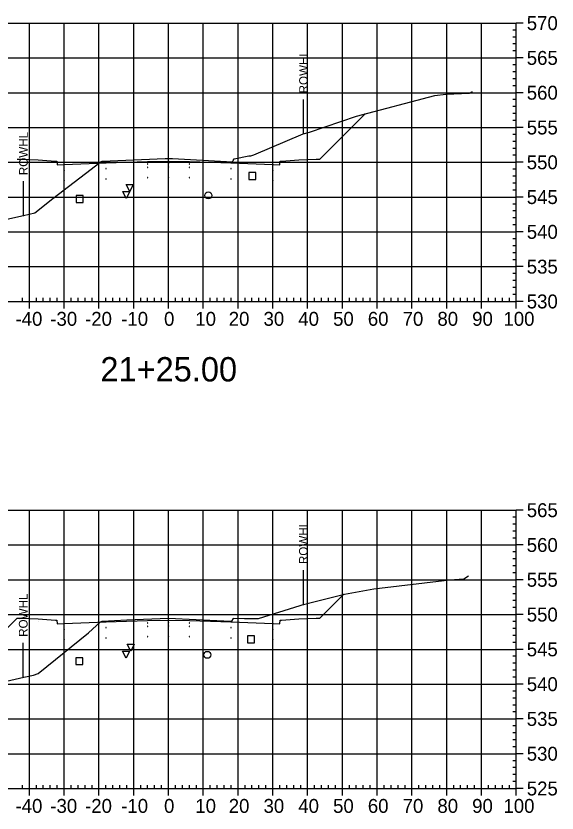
# Model space of a CAD drawing. Extents: x 708103 to 717568, y 374476 to 378707.
# Drawn here: x 709283.1 to 709438.7, y 377827.6 to 378056.7 of the extents above; entities that cross this region are included whole.
import ezdxf

# ---------------------------------------------------------------- set-up
doc = ezdxf.new("R2010")
doc.units = 0
for name, color, linetype in [('1', 7, 'Continuous'), ('10', 7, 'Continuous'), ('13', 7, 'Continuous'), ('14', 7, 'Continuous'), ('22', 7, 'Continuous'), ('4', 7, 'Continuous'), ('57', 7, 'Continuous'), ('Existing', 7, 'Continuous'), ('XS_Right_of_Way', 7, 'Continuous')]:
    doc.layers.add(name, color=color, linetype=linetype)

msp = doc.modelspace()

# ---------------------------------------------------------------- linework, layer by layer
for points in [[(709296.93, 378012.28), (709297.03, 378012.28), (709297.03, 378012.38), (709296.93, 378012.38)], [(709308.93, 378012.76), (709309.03, 378012.76), (709309.03, 378012.86), (709308.93, 378012.86)], [(709320.93, 378014.12), (709321.03, 378014.12), (709321.03, 378014.22), (709320.93, 378014.22)], [(709320.93, 378013.12), (709321.03, 378013.12), (709321.03, 378013.22), (709320.93, 378013.22)], [(709326.93, 378014.24), (709327.03, 378014.24), (709327.03, 378014.34), (709326.93, 378014.34)], [(709326.93, 378013.24), (709327.03, 378013.24), (709327.03, 378013.34), (709326.93, 378013.34)], [(709332.93, 378014.12), (709333.03, 378014.12), (709333.03, 378014.22), (709332.93, 378014.22)], [(709332.93, 378013.12), (709333.03, 378013.12), (709333.03, 378013.22), (709332.93, 378013.22)], [(709344.93, 378012.76), (709345.03, 378012.76), (709345.03, 378012.86), (709344.93, 378012.86)], [(709356.93, 378012.28), (709357.03, 378012.28), (709357.03, 378012.38), (709356.93, 378012.38)], [(709320.93, 378010.12), (709321.03, 378010.12), (709321.03, 378010.22), (709320.93, 378010.22)], [(709326.93, 378010.24), (709327.03, 378010.24), (709327.03, 378010.34), (709326.93, 378010.34)], [(709332.93, 378010.12), (709333.03, 378010.12), (709333.03, 378010.22), (709332.93, 378010.22)], [(709296.93, 378009.28), (709297.03, 378009.28), (709297.03, 378009.38), (709296.93, 378009.38)], [(709308.93, 378009.76), (709309.03, 378009.76), (709309.03, 378009.86), (709308.93, 378009.86)], [(709344.93, 378009.76), (709345.03, 378009.76), (709345.03, 378009.86), (709344.93, 378009.86)], [(709356.93, 378009.28), (709357.03, 378009.28), (709357.03, 378009.38), (709356.93, 378009.38)], [(709320.93, 377882.2), (709321.03, 377882.2), (709321.03, 377882.3), (709320.93, 377882.3)], [(709326.93, 377882.32), (709327.03, 377882.32), (709327.03, 377882.42), (709326.93, 377882.42)], [(709332.93, 377882.2), (709333.03, 377882.2), (709333.03, 377882.3), (709332.93, 377882.3)], [(709296.93, 377880.36), (709297.03, 377880.36), (709297.03, 377880.46), (709296.93, 377880.46)], [(709308.93, 377880.84), (709309.03, 377880.84), (709309.03, 377880.94), (709308.93, 377880.94)], [(709320.93, 377881.2), (709321.03, 377881.2), (709321.03, 377881.3), (709320.93, 377881.3)], [(709326.93, 377881.32), (709327.03, 377881.32), (709327.03, 377881.42), (709326.93, 377881.42)], [(709332.93, 377881.2), (709333.03, 377881.2), (709333.03, 377881.3), (709332.93, 377881.3)], [(709344.93, 377880.84), (709345.03, 377880.84), (709345.03, 377880.94), (709344.93, 377880.94)], [(709356.93, 377880.36), (709357.03, 377880.36), (709357.03, 377880.46), (709356.93, 377880.46)], [(709296.93, 377877.36), (709297.03, 377877.36), (709297.03, 377877.46), (709296.93, 377877.46)], [(709308.93, 377877.84), (709309.03, 377877.84), (709309.03, 377877.94), (709308.93, 377877.94)], [(709320.93, 377878.2), (709321.03, 377878.2), (709321.03, 377878.3), (709320.93, 377878.3)], [(709326.93, 377878.32), (709327.03, 377878.32), (709327.03, 377878.42), (709326.93, 377878.42)], [(709332.93, 377878.2), (709333.03, 377878.2), (709333.03, 377878.3), (709332.93, 377878.3)], [(709344.93, 377877.84), (709345.03, 377877.84), (709345.03, 377877.94), (709344.93, 377877.94)], [(709356.93, 377877.36), (709357.03, 377877.36), (709357.03, 377877.46), (709356.93, 377877.46)]]:
    msp.add_lwpolyline(points, close=True)
at = {"layer": '1'}
for points in [[(709315.82, 378006.27), (709314.82, 378008.27), (709316.82, 378008.27)], [(709314.84, 378004.23), (709313.84, 378006.23), (709315.84, 378006.23)], [(709316.13, 377874.14), (709315.13, 377876.14), (709317.13, 377876.14)], [(709314.76, 377872.08), (709313.76, 377874.08), (709315.76, 377874.08)]]:
    msp.add_lwpolyline(points, close=True, dxfattribs=at)
at = {"layer": '10'}
for points in [[(709300.41, 378003.08), (709302.41, 378003.08), (709302.41, 378005.08), (709300.41, 378005.08)], [(709300.33, 377870.24), (709302.33, 377870.24), (709302.33, 377872.24), (709300.33, 377872.24)]]:
    msp.add_lwpolyline(points, close=True, dxfattribs=at)
at = {"layer": '13'}
for centre in [(709338.42, 378005.12), (709338.14, 377873.06)]:
    msp.add_circle(centre, 1, dxfattribs=at)
at = {"layer": '14'}
for points in [[(709383.42, 378028.49), (709383.42, 378028.54), (709383.42, 378028.49), (709383.37, 378028.49), (709383.42, 378028.49), (709383.42, 378028.44), (709383.42, 378028.49), (709383.47, 378028.49)], [(709326.98, 378014.96), (709326.98, 378015.01), (709326.98, 378014.96), (709326.93, 378014.96), (709326.98, 378014.96), (709326.98, 378014.91), (709326.98, 378014.96), (709327.03, 378014.96)], [(709296.98, 378014), (709296.98, 378014.05), (709296.98, 378014), (709296.93, 378014), (709296.98, 378014), (709296.98, 378013.95), (709296.98, 378014), (709297.03, 378014)], [(709308.98, 378014.48), (709308.98, 378014.53), (709308.98, 378014.48), (709308.93, 378014.48), (709308.98, 378014.48), (709308.98, 378014.43), (709308.98, 378014.48), (709309.03, 378014.48)], [(709344.98, 378014.48), (709344.98, 378014.53), (709344.98, 378014.48), (709344.93, 378014.48), (709344.98, 378014.48), (709344.98, 378014.43), (709344.98, 378014.48), (709345.03, 378014.48)], [(709356.98, 378014), (709356.98, 378014.05), (709356.98, 378014), (709356.93, 378014), (709356.98, 378014), (709356.98, 378013.95), (709356.98, 378014), (709357.03, 378014)], [(709377.25, 377890.4), (709377.25, 377890.45), (709377.25, 377890.4), (709377.2, 377890.4), (709377.25, 377890.4), (709377.25, 377890.35), (709377.25, 377890.4), (709377.3, 377890.4)], [(709296.98, 377882.08), (709296.98, 377882.13), (709296.98, 377882.08), (709296.93, 377882.08), (709296.98, 377882.08), (709296.98, 377882.03), (709296.98, 377882.08), (709297.03, 377882.08)], [(709308.98, 377882.56), (709308.98, 377882.61), (709308.98, 377882.56), (709308.93, 377882.56), (709308.98, 377882.56), (709308.98, 377882.51), (709308.98, 377882.56), (709309.03, 377882.56)], [(709326.98, 377883.04), (709326.98, 377883.09), (709326.98, 377883.04), (709326.93, 377883.04), (709326.98, 377883.04), (709326.98, 377882.99), (709326.98, 377883.04), (709327.03, 377883.04)], [(709344.98, 377882.56), (709344.98, 377882.61), (709344.98, 377882.56), (709344.93, 377882.56), (709344.98, 377882.56), (709344.98, 377882.51), (709344.98, 377882.56), (709345.03, 377882.56)], [(709356.98, 377882.08), (709356.98, 377882.13), (709356.98, 377882.08), (709356.93, 377882.08), (709356.98, 377882.08), (709356.98, 377882.03), (709356.98, 377882.08), (709357.03, 377882.08)]]:
    msp.add_lwpolyline(points, dxfattribs=at)
at = {"layer": '22'}
for points in [[(709283.48, 378015.56), (709284.48, 378015.52), (709289.48, 378015.32), (709294.48, 378014.92), (709294.9, 378014.92), (709294.98, 378013.92), (709296.98, 378014), (709308.98, 378014.48), (709320.98, 378014.84), (709326.98, 378014.96), (709332.98, 378014.84), (709344.98, 378014.48), (709356.98, 378014), (709358.98, 378013.92), (709359.07, 378014.92), (709359.48, 378014.92), (709364.48, 378015.32), (709369.48, 378015.52), (709370.48, 378015.56), (709383.42, 378028.49)], [(709263.92, 377864.07), (709283.48, 377883.64), (709284.48, 377883.6), (709289.48, 377883.4), (709294.48, 377883), (709294.9, 377883), (709294.98, 377882), (709296.98, 377882.08), (709308.98, 377882.56), (709320.98, 377882.92), (709326.98, 377883.04), (709332.98, 377882.92), (709344.98, 377882.56), (709356.98, 377882.08), (709358.98, 377882), (709359.07, 377883), (709359.48, 377883), (709364.48, 377883.4), (709369.48, 377883.6), (709370.48, 377883.64), (709377.25, 377890.4)]]:
    msp.add_lwpolyline(points, dxfattribs=at)
at = {"layer": '4'}
for points in [[(709350.05, 378009.65), (709352.05, 378009.65), (709352.05, 378011.65), (709350.05, 378011.65)], [(709349.72, 377876.51), (709351.72, 377876.51), (709351.72, 377878.51), (709349.72, 377878.51)]]:
    msp.add_lwpolyline(points, close=True, dxfattribs=at)
at = {"layer": '57'}
for p, q in [((709226.98, 378054.63), (709426.98, 378054.63)), ((709286.98, 377974.63), (709286.98, 378054.63)), ((709296.98, 377974.63), (709296.98, 378054.63)), ((709306.98, 377974.63), (709306.98, 378054.63)), ((709316.98, 377974.63), (709316.98, 378054.63)), ((709326.98, 377974.63), (709326.98, 378054.63)), ((709336.98, 377974.63), (709336.98, 378054.63)), ((709346.98, 377974.63), (709346.98, 378054.63)), ((709356.98, 377974.63), (709356.98, 378054.63)), ((709366.98, 377974.63), (709366.98, 378054.63)), ((709376.98, 377974.63), (709376.98, 378054.63)), ((709386.98, 377974.63), (709386.98, 378054.63)), ((709396.98, 377974.63), (709396.98, 378054.63)), ((709406.98, 377974.63), (709406.98, 378054.63)), ((709416.98, 377974.63), (709416.98, 378054.63)), ((709426.98, 377974.63), (709426.98, 378054.63)), ((709426.98, 377974.63), (709426.98, 378054.63)), ((709428.98, 378054.63), (709426.98, 378054.63)), ((709426.98, 378052.63), (709425.98, 378052.63)), ((709426.98, 378050.63), (709425.98, 378050.63)), ((709426.98, 378048.63), (709425.98, 378048.63)), ((709426.98, 378046.63), (709425.98, 378046.63)), ((709226.98, 378044.63), (709426.98, 378044.63)), ((709428.98, 378044.63), (709426.98, 378044.63)), ((709426.98, 378042.63), (709425.98, 378042.63)), ((709426.98, 378040.63), (709425.98, 378040.63)), ((709426.98, 378038.63), (709425.98, 378038.63)), ((709426.98, 378036.63), (709425.98, 378036.63)), ((709226.98, 378034.63), (709426.98, 378034.63)), ((709428.98, 378034.63), (709426.98, 378034.63)), ((709426.98, 378032.63), (709425.98, 378032.63)), ((709426.98, 378030.63), (709425.98, 378030.63)), ((709426.98, 378028.63), (709425.98, 378028.63)), ((709426.98, 378026.63), (709425.98, 378026.63)), ((709226.98, 378024.63), (709426.98, 378024.63)), ((709428.98, 378024.63), (709426.98, 378024.63)), ((709426.98, 378022.63), (709425.98, 378022.63)), ((709426.98, 378020.63), (709425.98, 378020.63)), ((709426.98, 378018.63), (709425.98, 378018.63)), ((709226.98, 378014.63), (709426.98, 378014.63)), ((709426.98, 378016.63), (709425.98, 378016.63)), ((709428.98, 378014.63), (709426.98, 378014.63)), ((709426.98, 378012.63), (709425.98, 378012.63)), ((709426.98, 378010.63), (709425.98, 378010.63)), ((709426.98, 378008.63), (709425.98, 378008.63)), ((709426.98, 378006.63), (709425.98, 378006.63)), ((709226.98, 378004.63), (709426.98, 378004.63)), ((709428.98, 378004.63), (709426.98, 378004.63)), ((709426.98, 378002.63), (709425.98, 378002.63)), ((709426.98, 378000.63), (709425.98, 378000.63)), ((709426.98, 377998.63), (709425.98, 377998.63)), ((709426.98, 377996.63), (709425.98, 377996.63)), ((709226.98, 377994.63), (709426.98, 377994.63)), ((709428.98, 377994.63), (709426.98, 377994.63)), ((709426.98, 377992.63), (709425.98, 377992.63)), ((709426.98, 377990.63), (709425.98, 377990.63)), ((709426.98, 377988.63), (709425.98, 377988.63)), ((709426.98, 377986.63), (709425.98, 377986.63)), ((709226.98, 377984.63), (709426.98, 377984.63)), ((709426.98, 377982.63), (709425.98, 377982.63)), ((709428.98, 377984.63), (709426.98, 377984.63)), ((709426.98, 377980.63), (709425.98, 377980.63)), ((709426.98, 377978.63), (709425.98, 377978.63)), ((709284.98, 377974.63), (709284.98, 377975.63)), ((709288.98, 377974.63), (709288.98, 377975.63)), ((709290.98, 377974.63), (709290.98, 377975.63)), ((709292.98, 377974.63), (709292.98, 377975.63)), ((709294.98, 377974.63), (709294.98, 377975.63)), ((709298.98, 377974.63), (709298.98, 377975.63)), ((709300.98, 377974.63), (709300.98, 377975.63)), ((709302.98, 377974.63), (709302.98, 377975.63)), ((709304.98, 377974.63), (709304.98, 377975.63)), ((709308.98, 377974.63), (709308.98, 377975.63)), ((709310.98, 377974.63), (709310.98, 377975.63)), ((709312.98, 377974.63), (709312.98, 377975.63)), ((709314.98, 377974.63), (709314.98, 377975.63)), ((709318.98, 377974.63), (709318.98, 377975.63)), ((709320.98, 377974.63), (709320.98, 377975.63)), ((709322.98, 377974.63), (709322.98, 377975.63)), ((709324.98, 377974.63), (709324.98, 377975.63)), ((709328.98, 377974.63), (709328.98, 377975.63)), ((709330.98, 377974.63), (709330.98, 377975.63)), ((709332.98, 377974.63), (709332.98, 377975.63)), ((709334.98, 377974.63), (709334.98, 377975.63)), ((709338.98, 377974.63), (709338.98, 377975.63)), ((709340.98, 377974.63), (709340.98, 377975.63)), ((709342.98, 377974.63), (709342.98, 377975.63)), ((709344.98, 377974.63), (709344.98, 377975.63)), ((709348.98, 377974.63), (709348.98, 377975.63)), ((709350.98, 377974.63), (709350.98, 377975.63)), ((709352.98, 377974.63), (709352.98, 377975.63)), ((709354.98, 377974.63), (709354.98, 377975.63)), ((709358.98, 377974.63), (709358.98, 377975.63)), ((709360.98, 377974.63), (709360.98, 377975.63)), ((709362.98, 377974.63), (709362.98, 377975.63)), ((709364.98, 377974.63), (709364.98, 377975.63)), ((709368.98, 377974.63), (709368.98, 377975.63)), ((709370.98, 377974.63), (709370.98, 377975.63)), ((709372.98, 377974.63), (709372.98, 377975.63)), ((709374.98, 377974.63), (709374.98, 377975.63)), ((709378.98, 377974.63), (709378.98, 377975.63)), ((709380.98, 377974.63), (709380.98, 377975.63)), ((709382.98, 377974.63), (709382.98, 377975.63)), ((709384.98, 377974.63), (709384.98, 377975.63)), ((709388.98, 377974.63), (709388.98, 377975.63)), ((709390.98, 377974.63), (709390.98, 377975.63)), ((709392.98, 377974.63), (709392.98, 377975.63)), ((709394.98, 377974.63), (709394.98, 377975.63)), ((709398.98, 377974.63), (709398.98, 377975.63)), ((709400.98, 377974.63), (709400.98, 377975.63)), ((709402.98, 377974.63), (709402.98, 377975.63)), ((709404.98, 377974.63), (709404.98, 377975.63)), ((709408.98, 377974.63), (709408.98, 377975.63)), ((709410.98, 377974.63), (709410.98, 377975.63)), ((709412.98, 377974.63), (709412.98, 377975.63)), ((709414.98, 377974.63), (709414.98, 377975.63)), ((709418.98, 377974.63), (709418.98, 377975.63)), ((709420.98, 377974.63), (709420.98, 377975.63)), ((709422.98, 377974.63), (709422.98, 377975.63)), ((709424.98, 377974.63), (709424.98, 377975.63)), ((709426.98, 377976.63), (709425.98, 377976.63)), ((709226.98, 377974.63), (709426.98, 377974.63)), ((709226.98, 377974.63), (709426.98, 377974.63)), ((709286.98, 377972.63), (709286.98, 377974.63)), ((709296.98, 377972.63), (709296.98, 377974.63)), ((709306.98, 377972.63), (709306.98, 377974.63)), ((709316.98, 377972.63), (709316.98, 377974.63)), ((709326.98, 377972.63), (709326.98, 377974.63)), ((709336.98, 377972.63), (709336.98, 377974.63)), ((709346.98, 377972.63), (709346.98, 377974.63)), ((709356.98, 377972.63), (709356.98, 377974.63)), ((709366.98, 377972.63), (709366.98, 377974.63)), ((709376.98, 377972.63), (709376.98, 377974.63)), ((709386.98, 377972.63), (709386.98, 377974.63)), ((709396.98, 377972.63), (709396.98, 377974.63)), ((709406.98, 377972.63), (709406.98, 377974.63)), ((709416.98, 377972.63), (709416.98, 377974.63)), ((709426.98, 377972.63), (709426.98, 377974.63)), ((709428.98, 377974.63), (709426.98, 377974.63)), ((709226.98, 377914.63), (709426.98, 377914.63)), ((709286.98, 377834.63), (709286.98, 377914.63)), ((709296.98, 377834.63), (709296.98, 377914.63)), ((709306.98, 377834.63), (709306.98, 377914.63)), ((709316.98, 377834.63), (709316.98, 377914.63)), ((709326.98, 377834.63), (709326.98, 377914.63)), ((709336.98, 377834.63), (709336.98, 377914.63)), ((709346.98, 377834.63), (709346.98, 377914.63)), ((709356.98, 377834.63), (709356.98, 377914.63)), ((709366.98, 377834.63), (709366.98, 377914.63)), ((709376.98, 377834.63), (709376.98, 377914.63)), ((709386.98, 377834.63), (709386.98, 377914.63)), ((709396.98, 377834.63), (709396.98, 377914.63)), ((709406.98, 377834.63), (709406.98, 377914.63)), ((709416.98, 377834.63), (709416.98, 377914.63)), ((709426.98, 377834.63), (709426.98, 377914.63)), ((709426.98, 377834.63), (709426.98, 377914.63)), ((709428.98, 377914.63), (709426.98, 377914.63)), ((709426.98, 377912.63), (709425.98, 377912.63)), ((709426.98, 377910.63), (709425.98, 377910.63)), ((709426.98, 377908.63), (709425.98, 377908.63)), ((709226.98, 377904.63), (709426.98, 377904.63)), ((709426.98, 377906.63), (709425.98, 377906.63)), ((709428.98, 377904.63), (709426.98, 377904.63)), ((709426.98, 377902.63), (709425.98, 377902.63)), ((709426.98, 377900.63), (709425.98, 377900.63)), ((709426.98, 377898.63), (709425.98, 377898.63)), ((709426.98, 377896.63), (709425.98, 377896.63)), ((709226.98, 377894.63), (709426.98, 377894.63)), ((709428.98, 377894.63), (709426.98, 377894.63)), ((709426.98, 377892.63), (709425.98, 377892.63)), ((709426.98, 377890.63), (709425.98, 377890.63)), ((709426.98, 377888.63), (709425.98, 377888.63)), ((709426.98, 377886.63), (709425.98, 377886.63)), ((709226.98, 377884.63), (709426.98, 377884.63)), ((709428.98, 377884.63), (709426.98, 377884.63)), ((709426.98, 377882.63), (709425.98, 377882.63)), ((709426.98, 377880.63), (709425.98, 377880.63)), ((709426.98, 377878.63), (709425.98, 377878.63)), ((709426.98, 377876.63), (709425.98, 377876.63)), ((709226.98, 377874.63), (709426.98, 377874.63)), ((709426.98, 377872.63), (709425.98, 377872.63)), ((709428.98, 377874.63), (709426.98, 377874.63)), ((709426.98, 377870.63), (709425.98, 377870.63)), ((709426.98, 377868.63), (709425.98, 377868.63)), ((709426.98, 377866.63), (709425.98, 377866.63)), ((709226.98, 377864.63), (709426.98, 377864.63)), ((709428.98, 377864.63), (709426.98, 377864.63)), ((709426.98, 377862.63), (709425.98, 377862.63)), ((709426.98, 377860.63), (709425.98, 377860.63)), ((709426.98, 377858.63), (709425.98, 377858.63)), ((709426.98, 377856.63), (709425.98, 377856.63)), ((709226.98, 377854.63), (709426.98, 377854.63)), ((709428.98, 377854.63), (709426.98, 377854.63)), ((709426.98, 377852.63), (709425.98, 377852.63)), ((709426.98, 377850.63), (709425.98, 377850.63)), ((709426.98, 377848.63), (709425.98, 377848.63)), ((709426.98, 377846.63), (709425.98, 377846.63)), ((709226.98, 377844.63), (709426.98, 377844.63)), ((709428.98, 377844.63), (709426.98, 377844.63)), ((709426.98, 377842.63), (709425.98, 377842.63)), ((709426.98, 377840.63), (709425.98, 377840.63)), ((709426.98, 377838.63), (709425.98, 377838.63)), ((709426.98, 377836.63), (709425.98, 377836.63)), ((709226.98, 377834.63), (709426.98, 377834.63)), ((709226.98, 377834.63), (709426.98, 377834.63)), ((709284.98, 377834.63), (709284.98, 377835.63)), ((709286.98, 377832.63), (709286.98, 377834.63)), ((709288.98, 377834.63), (709288.98, 377835.63)), ((709290.98, 377834.63), (709290.98, 377835.63)), ((709292.98, 377834.63), (709292.98, 377835.63)), ((709294.98, 377834.63), (709294.98, 377835.63)), ((709296.98, 377832.63), (709296.98, 377834.63)), ((709298.98, 377834.63), (709298.98, 377835.63)), ((709300.98, 377834.63), (709300.98, 377835.63)), ((709302.98, 377834.63), (709302.98, 377835.63)), ((709304.98, 377834.63), (709304.98, 377835.63)), ((709306.98, 377832.63), (709306.98, 377834.63)), ((709308.98, 377834.63), (709308.98, 377835.63)), ((709310.98, 377834.63), (709310.98, 377835.63)), ((709312.98, 377834.63), (709312.98, 377835.63)), ((709314.98, 377834.63), (709314.98, 377835.63)), ((709316.98, 377832.63), (709316.98, 377834.63)), ((709318.98, 377834.63), (709318.98, 377835.63)), ((709320.98, 377834.63), (709320.98, 377835.63)), ((709322.98, 377834.63), (709322.98, 377835.63)), ((709324.98, 377834.63), (709324.98, 377835.63)), ((709326.98, 377832.63), (709326.98, 377834.63)), ((709328.98, 377834.63), (709328.98, 377835.63)), ((709330.98, 377834.63), (709330.98, 377835.63)), ((709332.98, 377834.63), (709332.98, 377835.63)), ((709334.98, 377834.63), (709334.98, 377835.63)), ((709336.98, 377832.63), (709336.98, 377834.63)), ((709338.98, 377834.63), (709338.98, 377835.63)), ((709340.98, 377834.63), (709340.98, 377835.63)), ((709342.98, 377834.63), (709342.98, 377835.63)), ((709344.98, 377834.63), (709344.98, 377835.63)), ((709346.98, 377832.63), (709346.98, 377834.63)), ((709348.98, 377834.63), (709348.98, 377835.63)), ((709350.98, 377834.63), (709350.98, 377835.63)), ((709352.98, 377834.63), (709352.98, 377835.63)), ((709354.98, 377834.63), (709354.98, 377835.63)), ((709356.98, 377832.63), (709356.98, 377834.63)), ((709358.98, 377834.63), (709358.98, 377835.63)), ((709360.98, 377834.63), (709360.98, 377835.63)), ((709362.98, 377834.63), (709362.98, 377835.63)), ((709364.98, 377834.63), (709364.98, 377835.63)), ((709366.98, 377832.63), (709366.98, 377834.63)), ((709368.98, 377834.63), (709368.98, 377835.63)), ((709370.98, 377834.63), (709370.98, 377835.63)), ((709372.98, 377834.63), (709372.98, 377835.63)), ((709374.98, 377834.63), (709374.98, 377835.63)), ((709376.98, 377832.63), (709376.98, 377834.63)), ((709378.98, 377834.63), (709378.98, 377835.63)), ((709380.98, 377834.63), (709380.98, 377835.63)), ((709382.98, 377834.63), (709382.98, 377835.63)), ((709384.98, 377834.63), (709384.98, 377835.63)), ((709386.98, 377832.63), (709386.98, 377834.63)), ((709388.98, 377834.63), (709388.98, 377835.63)), ((709390.98, 377834.63), (709390.98, 377835.63)), ((709392.98, 377834.63), (709392.98, 377835.63)), ((709394.98, 377834.63), (709394.98, 377835.63)), ((709396.98, 377832.63), (709396.98, 377834.63)), ((709398.98, 377834.63), (709398.98, 377835.63)), ((709400.98, 377834.63), (709400.98, 377835.63)), ((709402.98, 377834.63), (709402.98, 377835.63)), ((709404.98, 377834.63), (709404.98, 377835.63)), ((709406.98, 377832.63), (709406.98, 377834.63)), ((709408.98, 377834.63), (709408.98, 377835.63)), ((709410.98, 377834.63), (709410.98, 377835.63)), ((709412.98, 377834.63), (709412.98, 377835.63)), ((709414.98, 377834.63), (709414.98, 377835.63)), ((709416.98, 377832.63), (709416.98, 377834.63)), ((709418.98, 377834.63), (709418.98, 377835.63)), ((709420.98, 377834.63), (709420.98, 377835.63)), ((709422.98, 377834.63), (709422.98, 377835.63)), ((709424.98, 377834.63), (709424.98, 377835.63)), ((709426.98, 377832.63), (709426.98, 377834.63)), ((709428.98, 377834.63), (709426.98, 377834.63))]:
    msp.add_line(p, q, dxfattribs=at)
at = {"layer": 'Existing'}
for points in [[(709276.94, 377997.56), (709285.28, 377999.32), (709288.49, 378000.11), (709293.74, 378004.24), (709307.61, 378014.81), (709307.9, 378014.93), (709326.04, 378015.7), (709326.9, 378015.74), (709328.1, 378015.67), (709345.35, 378014.76), (709345.57, 378015.16), (709345.83, 378015.64), (709350.1, 378016.53), (709350.66, 378016.53), (709351.51, 378016.8), (709365.65, 378022.78), (709367.48, 378023.24), (709380.99, 378027.85), (709403.51, 378033.82), (709406.67, 378034.21), (709413.48, 378034.49), (709414.34, 378035)], [(709279.13, 377865.2), (709285.35, 377866.66), (709288.18, 377867.22), (709289.51, 377867.68), (709304, 377879.4), (709307.46, 377882.55), (709307.93, 377882.69), (709315.02, 377883.09), (709326.94, 377883.61), (709342.9, 377882.82), (709345.22, 377882.72), (709345.65, 377883.52), (709345.7, 377883.6), (709348.8, 377883.49), (709352.86, 377883.52), (709364.83, 377887.19), (709365.39, 377887.43), (709368.39, 377888.18), (709377.62, 377890.5), (709386.06, 377892.05), (709407.85, 377894.59), (709411.88, 377894.91), (709413.28, 377895.74)]]:
    msp.add_lwpolyline(points, dxfattribs=at)
at = {"layer": 'XS_Right_of_Way'}
for p, q in [((709365.73, 378032.67), (709365.73, 378022.67)), ((709285.2, 378009.16), (709285.2, 377999.16)), ((709365.69, 377897.36), (709365.69, 377887.36)), ((709285.13, 377876.47), (709285.13, 377866.47))]:
    msp.add_line(p, q, dxfattribs=at)

# ---------------------------------------------------------------- texts
at = {"layer": '1'}
msp.add_text('21+25.00', height=7, dxfattribs=at).set_placement((709307.39, 377951.63))
at = {"layer": '14'}
for p in [(709284.45, 378015.47), (709284.45, 378014.8), (709289.45, 378014.6), (709364.45, 378014.6), (709369.45, 378015.47), (709369.45, 378014.8), (709284.45, 377883.55), (709284.45, 377882.88), (709289.45, 377882.68), (709364.45, 377882.68), (709369.45, 377883.55), (709369.45, 377882.88)]:
    msp.add_text('+', height=0.1, dxfattribs=at).set_placement(p)
at = {"layer": '57'}
for s, p in [('570', (709429.98, 378052.63)), ('565', (709429.98, 378042.63)), ('560', (709429.98, 378032.63)), ('555', (709429.98, 378022.63)), ('550', (709429.98, 378012.63)), ('545', (709429.98, 378002.63)), ('540', (709429.98, 377992.63)), ('535', (709429.98, 377982.63)), ('530', (709429.98, 377972.63)), ('-40', (709282.98, 377967.63)), ('-30', (709292.98, 377967.63)), ('-20', (709302.98, 377967.63)), ('-10', (709313.37, 377967.63)), ('0', (709325.69, 377967.63)), ('10', (709334.68, 377967.63)), ('20', (709344.29, 377967.63)), ('30', (709354.29, 377967.63)), ('40', (709364.29, 377967.63)), ('50', (709374.29, 377967.63)), ('60', (709384.29, 377967.63)), ('70', (709394.29, 377967.63)), ('80', (709404.29, 377967.63)), ('90', (709414.29, 377967.63)), ('100', (709423.28, 377967.63)), ('565', (709429.98, 377912.63)), ('560', (709429.98, 377902.63)), ('555', (709429.98, 377892.63)), ('550', (709429.98, 377882.63)), ('545', (709429.98, 377872.63)), ('540', (709429.98, 377862.63)), ('535', (709429.98, 377852.63)), ('530', (709429.98, 377842.63)), ('525', (709429.98, 377832.63)), ('-40', (709282.98, 377827.63)), ('-30', (709292.98, 377827.63)), ('-20', (709302.98, 377827.63)), ('-10', (709313.37, 377827.63)), ('0', (709325.69, 377827.63)), ('10', (709334.68, 377827.63)), ('20', (709344.29, 377827.63)), ('30', (709354.29, 377827.63)), ('40', (709364.29, 377827.63)), ('50', (709374.29, 377827.63)), ('60', (709384.29, 377827.63)), ('70', (709394.29, 377827.63)), ('80', (709404.29, 377827.63)), ('90', (709414.29, 377827.63)), ('100', (709423.28, 377827.63))]:
    msp.add_text(s, height=4, dxfattribs=at).set_placement(p)
at = {"layer": 'XS_Right_of_Way'}
for p in [(709367.05, 378034.43), (709286.52, 378010.92), (709367.01, 377899.13), (709286.45, 377878.23)]:
    msp.add_text('ROWHL', height=2.5, rotation=90, dxfattribs=at).set_placement(p)

doc.saveas('drawing.dxf')
